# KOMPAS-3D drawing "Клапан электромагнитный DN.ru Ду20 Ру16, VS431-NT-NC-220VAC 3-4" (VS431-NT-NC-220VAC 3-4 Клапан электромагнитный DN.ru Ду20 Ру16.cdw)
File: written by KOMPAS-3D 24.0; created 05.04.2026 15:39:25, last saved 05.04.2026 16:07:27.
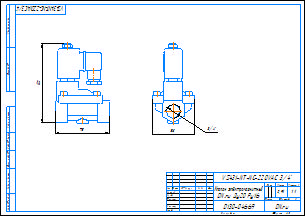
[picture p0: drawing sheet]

Document properties: c3d_UniqueCompID: ef56311e-7521-43dc-8291-0e6108b3d81d; Автор: artio; Класс точности: c; Знак неуказанной шероховатости: Шероховатость не задана; Рассекать на разрезах: Да; Автор: artio; Форматы листов документа: A3; Полное имя файла: VS431-NT-NC-220VAC 3-4 Клапан электромагнитный DN.ru Ду20 Ру16.m3d; Масса: 0.907; Наименование: Клапан электромагнитный DN.ru Ду20 Ру16; Количество листов документа: 1; Примечание: D130-04669

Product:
- Body: Тело 1  | qty 1
    Масса: 1.198355
- Part/product: Клапан электромагнитный DN.ru Ду20 Ру16  | designation VS431-NT-NC-220VAC 3-4
    Масса: 0.907
    Раздел спецификации: Прочие изделия
    Примечание: D130-04669
    additional columns: ef56311e-7521-43dc-8291-0e6108b3d81d; artio; c; Шероховатость не задана; Да

Views: Вид 1, Спереди, Проекционный вид 2
Referenced files in C:\Users\artio\OneDrive\Рабочий стол\Клапан электромагнитный DN.ru\VS431\VS431-ET-NC\: VS431-ET-NC-220VAC 3-4 Клапан электромагнитный DN.ru Ду20 Ру16.m3d
Referenced files in C:\Users\artio\OneDrive\Рабочий стол\Клапан электромагнитный DN.ru\VS431\VS431-NT-NC\: VS431-NT-NC-220VAC 3-4 Клапан электромагнитный DN.ru Ду20 Ру16.m3d, VS431-NT-NC-220VAC 3-4 Клапан электромагнитный DN.ru Ду20 Ру16.cdw
Referenced files in C:\Users\artio\OneDrive\Рабочий стол\Клапан электромагнитный DN.ru\VS431\VS431-NT-NC\VS431-NT-NC-220VAC\Ду20\: VS431-NT-NC-220VAC 3-4 Клапан электромагнитный DN.ru Ду20 Ру16.m3d
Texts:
  VS431-NT-NC-220VAC 3-4
  Клапан электромагнитный
  DN.ru Ду20 Ру16
  VS431-NT-NC-220VAC 3/4"
  VS431-NT-NC-220VAC 3/4"-
  Клапан электромагнитный DN.ru Ду20 Ру16
  VS431-NT-NC-220VAC 3-4 Клапан электромагнитный DN.ru Ду20 Ру16
Dimensions and other numbers on the sheet: 0; 3; 2; 4; 58; 3/4"; 75; 110; 1:1; 1; 0,91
